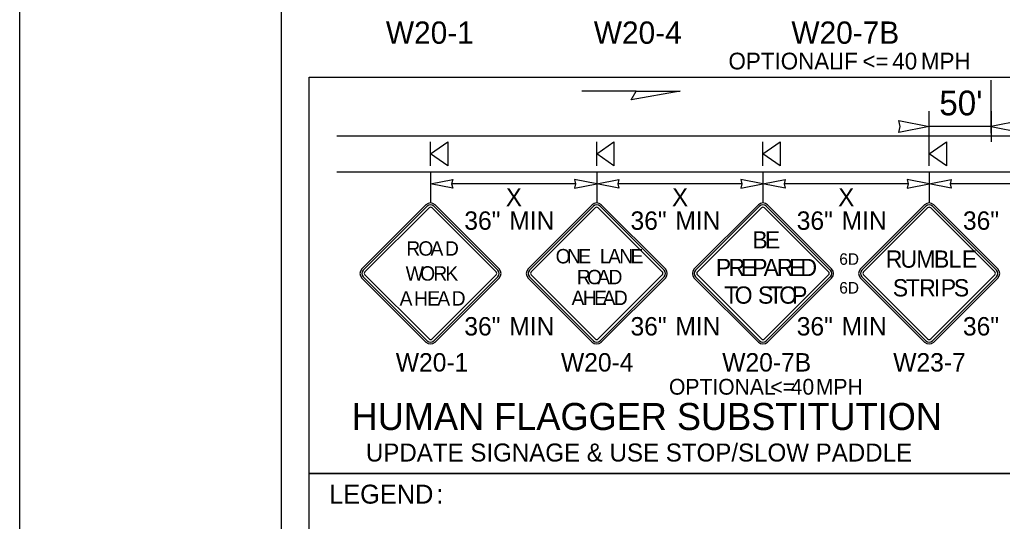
# Model space of a CAD drawing. Extents: x 99999.1 to 100095.7, y 99995 to 100010.7.
# Drawn here: x 100039.062 to 100042.586, y 100003.046 to 100004.846 of the extents above; entities that cross this region are included whole.
import ezdxf

# ---------------------------------------------------------------- set-up
doc = ezdxf.new("R2010")
doc.units = 0
for name, color, linetype in [('RD_ED_ShoulderPavedEdge', 7, 'Continuous'), ('RD_MK_LineEdgeWhite', 7, 'Continuous'), ('SH_DE_DetailHeading2Text', 7, 'Continuous'), ('SH_GI_PlotLimits', 7, 'Continuous'), ('SH_GI_SheetBorder', 7, 'Continuous'), ('TR_SN_ConstructionSigns', 7, 'Continuous'), ('TR_WZ_PortableSignMountBlk-Org', 7, 'Continuous'), ('TR_WZ_WorkZoneDetails', 7, 'Continuous'), ('TR_WZ_WorkZoneTextCurrent', 7, 'Continuous')]:
    doc.layers.add(name, color=color, linetype=linetype)

msp = doc.modelspace()

# ---------------------------------------------------------------- linework, layer by layer
at = {"layer": 'RD_ED_ShoulderPavedEdge'}
msp.add_line((100040.2, 100004.2992), (100043.6825, 100004.2992), dxfattribs=at)
at = {"layer": 'RD_MK_LineEdgeWhite'}
msp.add_line((100040.2, 100004.4284), (100043.6825, 100004.4284), dxfattribs=at)
at = {"layer": 'SH_GI_PlotLimits'}
msp.add_lwpolyline([(100039.0625, 99999.6875), (100056.0625, 99999.6875), (100056.0625, 100010.6875), (100039.0625, 100010.6875)], close=True, dxfattribs=at)
at = {"layer": 'SH_GI_SheetBorder'}
msp.add_line((100040, 100010.375), (100040, 100000), dxfattribs=at)
at = {"layer": 'TR_SN_ConstructionSigns'}
for p, q in [((100040.5193, 100004.1813), (100040.2896, 100003.9516)), ((100040.5239, 100004.1768), (100040.2942, 100003.9471)), ((100040.3006, 100003.9407), (100040.5303, 100004.1704)), ((100040.5412, 100004.1704), (100040.7709, 100003.9407)), ((100040.7773, 100003.9471), (100040.5476, 100004.1768)), ((100040.7818, 100003.9516), (100040.5521, 100004.1813)), ((100041.1153, 100004.1813), (100040.8856, 100003.9516)), ((100041.1198, 100004.1768), (100040.8901, 100003.9471)), ((100040.8965, 100003.9407), (100041.1262, 100004.1704)), ((100041.1371, 100004.1704), (100041.3668, 100003.9407)), ((100041.3732, 100003.9471), (100041.1435, 100004.1768)), ((100041.3778, 100003.9516), (100041.1481, 100004.1813)), ((100041.7112, 100004.1813), (100041.4815, 100003.9516)), ((100041.7158, 100004.1768), (100041.4861, 100003.9471)), ((100041.4924, 100003.9407), (100041.7221, 100004.1704)), ((100041.7331, 100004.1704), (100041.9628, 100003.9407)), ((100041.9691, 100003.9471), (100041.7395, 100004.1768)), ((100041.9737, 100003.9516), (100041.744, 100004.1813)), ((100042.3071, 100004.1813), (100042.0774, 100003.9516)), ((100042.3117, 100004.1768), (100042.082, 100003.9471)), ((100042.0884, 100003.9407), (100042.3181, 100004.1704)), ((100042.329, 100004.1704), (100042.5587, 100003.9407)), ((100042.5651, 100003.9471), (100042.3354, 100004.1768)), ((100042.5696, 100003.9516), (100042.3399, 100004.1813)), ((100040.2896, 100003.9188), (100040.5193, 100003.6891)), ((100040.2942, 100003.9234), (100040.5239, 100003.6937)), ((100040.5303, 100003.7), (100040.3006, 100003.9297)), ((100040.7709, 100003.9297), (100040.5412, 100003.7)), ((100040.5476, 100003.6937), (100040.7773, 100003.9234)), ((100040.5521, 100003.6891), (100040.7818, 100003.9188)), ((100040.8856, 100003.9188), (100041.1153, 100003.6891)), ((100040.8901, 100003.9234), (100041.1198, 100003.6937)), ((100041.1262, 100003.7), (100040.8965, 100003.9297)), ((100041.3668, 100003.9297), (100041.1371, 100003.7)), ((100041.1435, 100003.6937), (100041.3732, 100003.9234)), ((100041.1481, 100003.6891), (100041.3778, 100003.9188)), ((100041.4815, 100003.9188), (100041.7112, 100003.6891)), ((100041.4861, 100003.9234), (100041.7158, 100003.6937)), ((100041.7221, 100003.7), (100041.4924, 100003.9297)), ((100041.9628, 100003.9297), (100041.7331, 100003.7)), ((100041.7395, 100003.6937), (100041.9691, 100003.9234)), ((100041.744, 100003.6891), (100041.9737, 100003.9188)), ((100042.0774, 100003.9188), (100042.3071, 100003.6891)), ((100042.082, 100003.9234), (100042.3117, 100003.6937)), ((100042.3181, 100003.7), (100042.0884, 100003.9297)), ((100042.5587, 100003.9297), (100042.329, 100003.7)), ((100042.3354, 100003.6937), (100042.5651, 100003.9234)), ((100042.3399, 100003.6891), (100042.5696, 100003.9188))]:
    msp.add_line(p, q, dxfattribs=at)
for centre, radius, start, end in [((100040.5357, 100004.1649), 0.0232, 45, 135), ((100040.5357, 100004.1649), 0.0168, 45, 135), ((100040.5357, 100004.1649), 0.00773, 45, 135), ((100041.1317, 100004.1649), 0.0232, 45, 135), ((100041.1317, 100004.1649), 0.0168, 45, 135), ((100041.1317, 100004.1649), 0.00773, 45, 135), ((100041.7276, 100004.1649), 0.0232, 45, 135), ((100041.7276, 100004.1649), 0.0168, 45, 135), ((100041.7276, 100004.1649), 0.00773, 45, 135), ((100042.3235, 100004.1649), 0.0232, 45, 135), ((100042.3235, 100004.1649), 0.0168, 45, 135), ((100042.3235, 100004.1649), 0.00773, 45, 135), ((100040.306, 100003.9352), 0.0232, 135, 225), ((100040.306, 100003.9352), 0.0168, 135, 225), ((100040.306, 100003.9352), 0.00773, 135, 225), ((100040.7654, 100003.9352), 0.00773, 315, 45), ((100040.7654, 100003.9352), 0.0168, 315, 45), ((100040.7654, 100003.9352), 0.0232, 315, 45), ((100040.902, 100003.9352), 0.0232, 135, 225), ((100040.902, 100003.9352), 0.0168, 135, 225), ((100040.902, 100003.9352), 0.00773, 135, 225), ((100041.3614, 100003.9352), 0.00773, 315, 45), ((100041.3614, 100003.9352), 0.0168, 315, 45), ((100041.3614, 100003.9352), 0.0232, 315, 45), ((100041.4979, 100003.9352), 0.0232, 135, 225), ((100041.4979, 100003.9352), 0.0168, 135, 225), ((100041.4979, 100003.9352), 0.00773, 135, 225), ((100041.9573, 100003.9352), 0.00773, 315, 45), ((100041.9573, 100003.9352), 0.0168, 315, 45), ((100041.9573, 100003.9352), 0.0232, 315, 45), ((100042.0938, 100003.9352), 0.0232, 135, 225), ((100042.0938, 100003.9352), 0.0168, 135, 225), ((100042.0938, 100003.9352), 0.00773, 135, 225), ((100042.5532, 100003.9352), 0.00773, 315, 45), ((100042.5532, 100003.9352), 0.0168, 315, 45), ((100042.5532, 100003.9352), 0.0232, 315, 45), ((100040.5357, 100003.7055), 0.0232, 225, 315), ((100040.5357, 100003.7055), 0.0168, 225, 315), ((100040.5357, 100003.7055), 0.00773, 225, 315), ((100041.1317, 100003.7055), 0.0232, 225, 315), ((100041.1317, 100003.7055), 0.0168, 225, 315), ((100041.1317, 100003.7055), 0.00773, 225, 315), ((100041.7276, 100003.7055), 0.0232, 225, 315), ((100041.7276, 100003.7055), 0.0168, 225, 315), ((100041.7276, 100003.7055), 0.00773, 225, 315), ((100042.3235, 100003.7055), 0.0232, 225, 315), ((100042.3235, 100003.7055), 0.0168, 225, 315), ((100042.3235, 100003.7055), 0.00773, 225, 315)]:
    msp.add_arc(centre, radius, start, end, dxfattribs=at)
at = {"layer": 'TR_WZ_PortableSignMountBlk-Org'}
for p, q in [((100040.5357, 100004.3208), (100040.5357, 100004.4069)), ((100041.1317, 100004.3208), (100041.1317, 100004.4069)), ((100041.7276, 100004.3208), (100041.7276, 100004.4069)), ((100042.3235, 100004.3208), (100042.3235, 100004.4069))]:
    msp.add_line(p, q, dxfattribs=at)
for points in [[(100040.5357, 100004.3638), (100040.5976, 100004.4069), (100040.5976, 100004.3208)], [(100041.1317, 100004.3638), (100041.1935, 100004.4069), (100041.1935, 100004.3208)], [(100041.7276, 100004.3638), (100041.7895, 100004.4069), (100041.7895, 100004.3208)], [(100042.3235, 100004.3638), (100042.3854, 100004.4069), (100042.3854, 100004.3208)]]:
    msp.add_lwpolyline(points, close=True, dxfattribs=at)
at = {"layer": 'TR_WZ_WorkZoneDetails'}
for p, q in [((100042.5458, 100004.4384), (100042.5458, 100004.6291)), ((100041.2726, 100004.5891), (100041.078, 100004.5891)), ((100042.3235, 100004.4069), (100042.3235, 100004.5179)), ((100042.5458, 100004.5179), (100042.5458, 100004.4069)), ((100042.5458, 100004.4624), (100042.3235, 100004.4624)), ((100040.5357, 100004.2994), (100040.5357, 100004.1881)), ((100041.1317, 100004.2994), (100041.1317, 100004.1881)), ((100041.7276, 100004.2992), (100041.7276, 100004.1881)), ((100042.3235, 100004.2992), (100042.3235, 100004.1881)), ((100041.056, 100004.2562), (100040.6114, 100004.2562)), ((100041.6519, 100004.2562), (100041.2073, 100004.2562)), ((100042.2479, 100004.2562), (100041.8033, 100004.2562)), ((100042.8438, 100004.2562), (100042.3992, 100004.2562))]:
    msp.add_line(p, q, dxfattribs=at)
for points in [[(100041.4313, 100004.5891), (100041.2546, 100004.558), (100041.2726, 100004.5891)], [(100042.3235, 100004.4624), (100042.2143, 100004.441), (100042.2194, 100004.4624), (100042.2143, 100004.4838)], [(100042.5458, 100004.4624), (100042.655, 100004.441), (100042.6499, 100004.4624), (100042.655, 100004.4838)], [(100040.5357, 100004.2562), (100040.6151, 100004.2717), (100040.6114, 100004.2562), (100040.6151, 100004.2406)], [(100041.1317, 100004.2562), (100041.0523, 100004.2717), (100041.056, 100004.2562), (100041.0523, 100004.2406)], [(100041.1317, 100004.2562), (100041.211, 100004.2717), (100041.2073, 100004.2562), (100041.211, 100004.2406)], [(100041.7276, 100004.2562), (100041.6482, 100004.2717), (100041.6519, 100004.2562), (100041.6482, 100004.2406)], [(100041.7276, 100004.2562), (100041.807, 100004.2717), (100041.8033, 100004.2562), (100041.807, 100004.2406)], [(100042.3235, 100004.2562), (100042.2442, 100004.2717), (100042.2479, 100004.2562), (100042.2442, 100004.2406)], [(100042.3235, 100004.2562), (100042.4029, 100004.2717), (100042.3992, 100004.2562), (100042.4029, 100004.2406)]]:
    msp.add_lwpolyline(points, close=True, dxfattribs=at)
at = {"layer": 'TR_WZ_WorkZoneTextCurrent'}
for points in [[(100040.1, 100004.6391), (100043.7858, 100004.6391), (100043.7858, 100003.2174), (100040.1, 100003.2174)], [(100040.1, 100003.2174), (100043.2886, 100003.2174), (100043.2886, 100001.1759), (100040.1, 100001.1759)]]:
    msp.add_lwpolyline(points, close=True, dxfattribs=at)

# ---------------------------------------------------------------- texts
at = {"layer": 'SH_DE_DetailHeading2Text'}
msp.add_text('HUMAN FLAGGER SUBSTITUTION', height=0.09689, rotation=360, dxfattribs=at).set_placement((100040.2529, 100003.3735))
at = {"layer": 'TR_SN_ConstructionSigns'}
for s, height, p in [('W20-1', 0.08, (100040.3757, 100004.7592)), ('W20-4', 0.08, (100041.1212, 100004.7592)), ('W20-7B', 0.08, (100041.8296, 100004.7592)), ('OPTIONAL', 0.06, (100041.604, 100004.6672)), ('40', 0.06, (100042.1913, 100004.6672)), ('IF', 0.06, (100041.9964, 100004.6672)), ('<=', 0.06, (100042.0842, 100004.6672)), ('MPH', 0.06, (100042.2939, 100004.6672)), ('36"', 0.066, (100040.6568, 100004.0918)), ('MIN', 0.066, (100040.8177, 100004.0918)), ('36"', 0.066, (100041.2527, 100004.0918)), ('MIN', 0.066, (100041.4136, 100004.0918)), ('36"', 0.066, (100041.8487, 100004.0918)), ('MIN', 0.066, (100042.0096, 100004.0918)), ('36"', 0.066, (100042.4446, 100004.0918)), ('36"', 0.066, (100040.6568, 100003.7126)), ('MIN', 0.066, (100040.8177, 100003.7126)), ('36"', 0.066, (100041.2527, 100003.7126)), ('MIN', 0.066, (100041.4136, 100003.7126)), ('36"', 0.066, (100041.8487, 100003.7126)), ('MIN', 0.066, (100042.0096, 100003.7126)), ('36"', 0.066, (100042.4446, 100003.7126)), ('W20-1', 0.066, (100040.4112, 100003.5833)), ('W20-4', 0.066, (100041.0034, 100003.5833)), ('W20-7B', 0.066, (100041.5816, 100003.5833)), ('W23-7', 0.066, (100042.1947, 100003.5833)), ('OPTIONAL', 0.05657, (100041.3906, 100003.5003)), ('<=', 0.05657, (100041.7538, 100003.5003)), ('40', 0.05657, (100041.8271, 100003.5003)), ('MPH', 0.05657, (100041.9172, 100003.5003))]:
    msp.add_text(s, height=height, rotation=360, dxfattribs=at).set_placement(p)
for s, height, p in [('B', 0.0619, (100041.6894, 100004.0247)), ('E', 0.0619, (100041.7342, 100004.0247)), ('R', 0.0516, (100040.449, 100003.999)), ('O', 0.0516, (100040.4921, 100003.999)), ('A', 0.0516, (100040.5356, 100003.999)), ('D', 0.0516, (100040.5874, 100003.999)), ('O', 0.0516, (100040.9842, 100003.9713)), ('N', 0.0516, (100041.0249, 100003.9713)), ('E', 0.0516, (100041.0652, 100003.9713)), ('L', 0.0516, (100041.143, 100003.9713)), ('A', 0.0516, (100041.1724, 100003.9713)), ('N', 0.0516, (100041.2126, 100003.9713)), ('E', 0.0516, (100041.2528, 100003.9713)), ('6D', 0.04125, (100042.0014, 100003.9662)), ('R', 0.0619, (100042.1679, 100003.9558)), ('U', 0.0619, (100042.2205, 100003.9558)), ('M', 0.0619, (100042.2774, 100003.9558)), ('B', 0.0619, (100042.3406, 100003.9558)), ('L', 0.0619, (100042.3931, 100003.9558)), ('E', 0.0619, (100042.4408, 100003.9558)), ('W', 0.0516, (100040.4464, 100003.9094)), ('O', 0.0516, (100040.4985, 100003.9094)), ('R', 0.0516, (100040.5457, 100003.9094)), ('K', 0.0516, (100040.589, 100003.9094)), ('P', 0.0619, (100041.5586, 100003.9257)), ('R', 0.0619, (100041.6041, 100003.9257)), ('E', 0.0619, (100041.648, 100003.9257)), ('P', 0.0619, (100041.6888, 100003.9257)), ('A', 0.0619, (100041.73, 100003.9257)), ('R', 0.0619, (100041.7773, 100003.9257)), ('E', 0.0619, (100041.8212, 100003.9257)), ('D', 0.0619, (100041.862, 100003.9257)), ('R', 0.0516, (100041.0605, 100003.8965)), ('O', 0.0516, (100041.0971, 100003.8965)), ('A', 0.0516, (100041.1337, 100003.8965)), ('D', 0.0516, (100041.1739, 100003.8965)), ('T', 0.0619, (100041.5888, 100003.8267)), ('O', 0.0619, (100041.626, 100003.8267)), ('S', 0.0619, (100041.7097, 100003.8267)), ('T', 0.0619, (100041.7486, 100003.8267)), ('O', 0.0619, (100041.7858, 100003.8267)), ('P', 0.0619, (100041.8318, 100003.8267)), ('6D', 0.04125, (100042.0014, 100003.863)), ('S', 0.0619, (100042.193, 100003.8527)), ('T', 0.0619, (100042.24, 100003.8527)), ('R', 0.0619, (100042.2876, 100003.8527)), ('I', 0.0619, (100042.3402, 100003.8527)), ('P', 0.0619, (100042.365, 100003.8527)), ('S', 0.0619, (100042.412, 100003.8527)), ('A', 0.0516, (100040.4249, 100003.8199)), ('H', 0.0516, (100040.4764, 100003.8199)), ('E', 0.0516, (100040.5239, 100003.8199)), ('A', 0.0516, (100040.56, 100003.8199)), ('D', 0.0516, (100040.6115, 100003.8199)), ('A', 0.0516, (100041.0414, 100003.8218)), ('H', 0.0516, (100041.0817, 100003.8218)), ('E', 0.0516, (100041.1219, 100003.8218)), ('A', 0.0516, (100041.1528, 100003.8218)), ('D', 0.0516, (100041.193, 100003.8218))]:
    msp.add_text(s, height=height, dxfattribs=at).set_placement(p)
at = {"layer": 'TR_WZ_WorkZoneTextCurrent'}
for s, height, p in [("50'", 0.08889, (100042.3599, 100004.5024)), ('X', 0.0646, (100040.8057, 100004.1765)), ('X', 0.0646, (100041.4016, 100004.1765)), ('X', 0.0646, (100041.9975, 100004.1765)), ('UPDATE SIGNAGE & USE STOP/SLOW PADDLE', 0.064593, (100040.304, 100003.2604))]:
    msp.add_text(s, height=height, dxfattribs=at).set_placement(p)
for s, p in [('LEGEND', (100040.172, 100003.1094)), (':', (100040.5568, 100003.1094))]:
    msp.add_text(s, height=0.068, rotation=360, dxfattribs=at).set_placement(p)

doc.saveas('drawing.dxf')
